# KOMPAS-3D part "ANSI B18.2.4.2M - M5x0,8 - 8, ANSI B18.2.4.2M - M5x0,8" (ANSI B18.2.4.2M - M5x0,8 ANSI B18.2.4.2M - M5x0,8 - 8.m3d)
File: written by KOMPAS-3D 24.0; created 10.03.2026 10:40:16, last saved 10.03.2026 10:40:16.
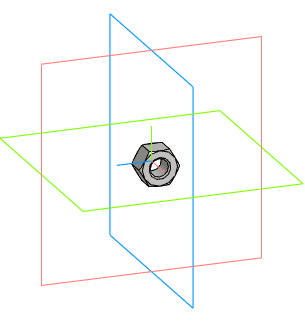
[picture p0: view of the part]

Document properties: Автор: R2D2; Полное имя файла: C:\Users\R2D2\Downloads\ANSI B18.2.4.2M - M5x0,8 ANSI B18.2.4.2M - M5x0,8 - 8.m3d

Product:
- Body: Solid1  | qty 1
- Part/product: ANSI B18.2.4.2M - M5x0,8 - 8  | designation ANSI B18.2.4.2M - M5x0,8
    Комментарий: Типы метрических   шестигранных гаек   2
    additional columns: Сталь, мягкая

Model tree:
1. Solid1  (labels: Solid1)

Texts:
  ANSI B18.2.4.2M - M5x0,8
